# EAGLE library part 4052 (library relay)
RELAY 2 x switch, Finder
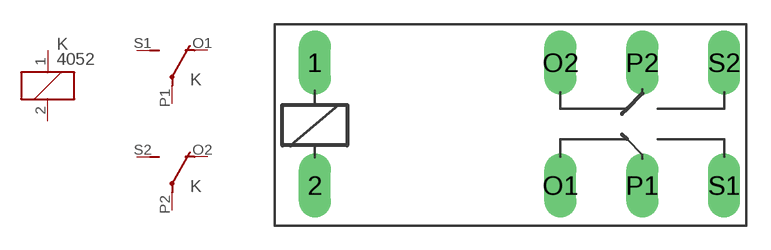
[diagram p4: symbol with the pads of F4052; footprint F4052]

Designator prefix K; gates 1=K 2=U 3=U

## 4052 (OC_FARNELL: unknown; OC_NEWARK: unknown)  [F4052]
1  1:1  pas
2  1:2  pas
O1  2:O  pas
O2  3:O  pas
P1  2:P  pas
P2  3:P  pas
S1  2:S  pas
S2  3:S  pas

## Footprint F4052 (pad centres in mm)
RELAY 2 x switch, Finder
drill 1.321 long: 1 -3.81,3.81; 2 -3.81,-3.81; O1 11.43,-3.81; O2 11.43,3.81; P1 16.51,-3.81; P2 16.51,3.81; S1 21.59,-3.81; S2 21.59,3.81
